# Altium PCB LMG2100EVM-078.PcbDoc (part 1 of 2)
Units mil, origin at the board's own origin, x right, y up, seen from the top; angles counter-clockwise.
Board outline 2400 x 2700 mil, 4 copper layers (Top Layer, MidLayer1, MidLayer2, Bottom Layer), stack 61.2 mil thick; 76 components, 27 nets, 153 pads, 244 vias.
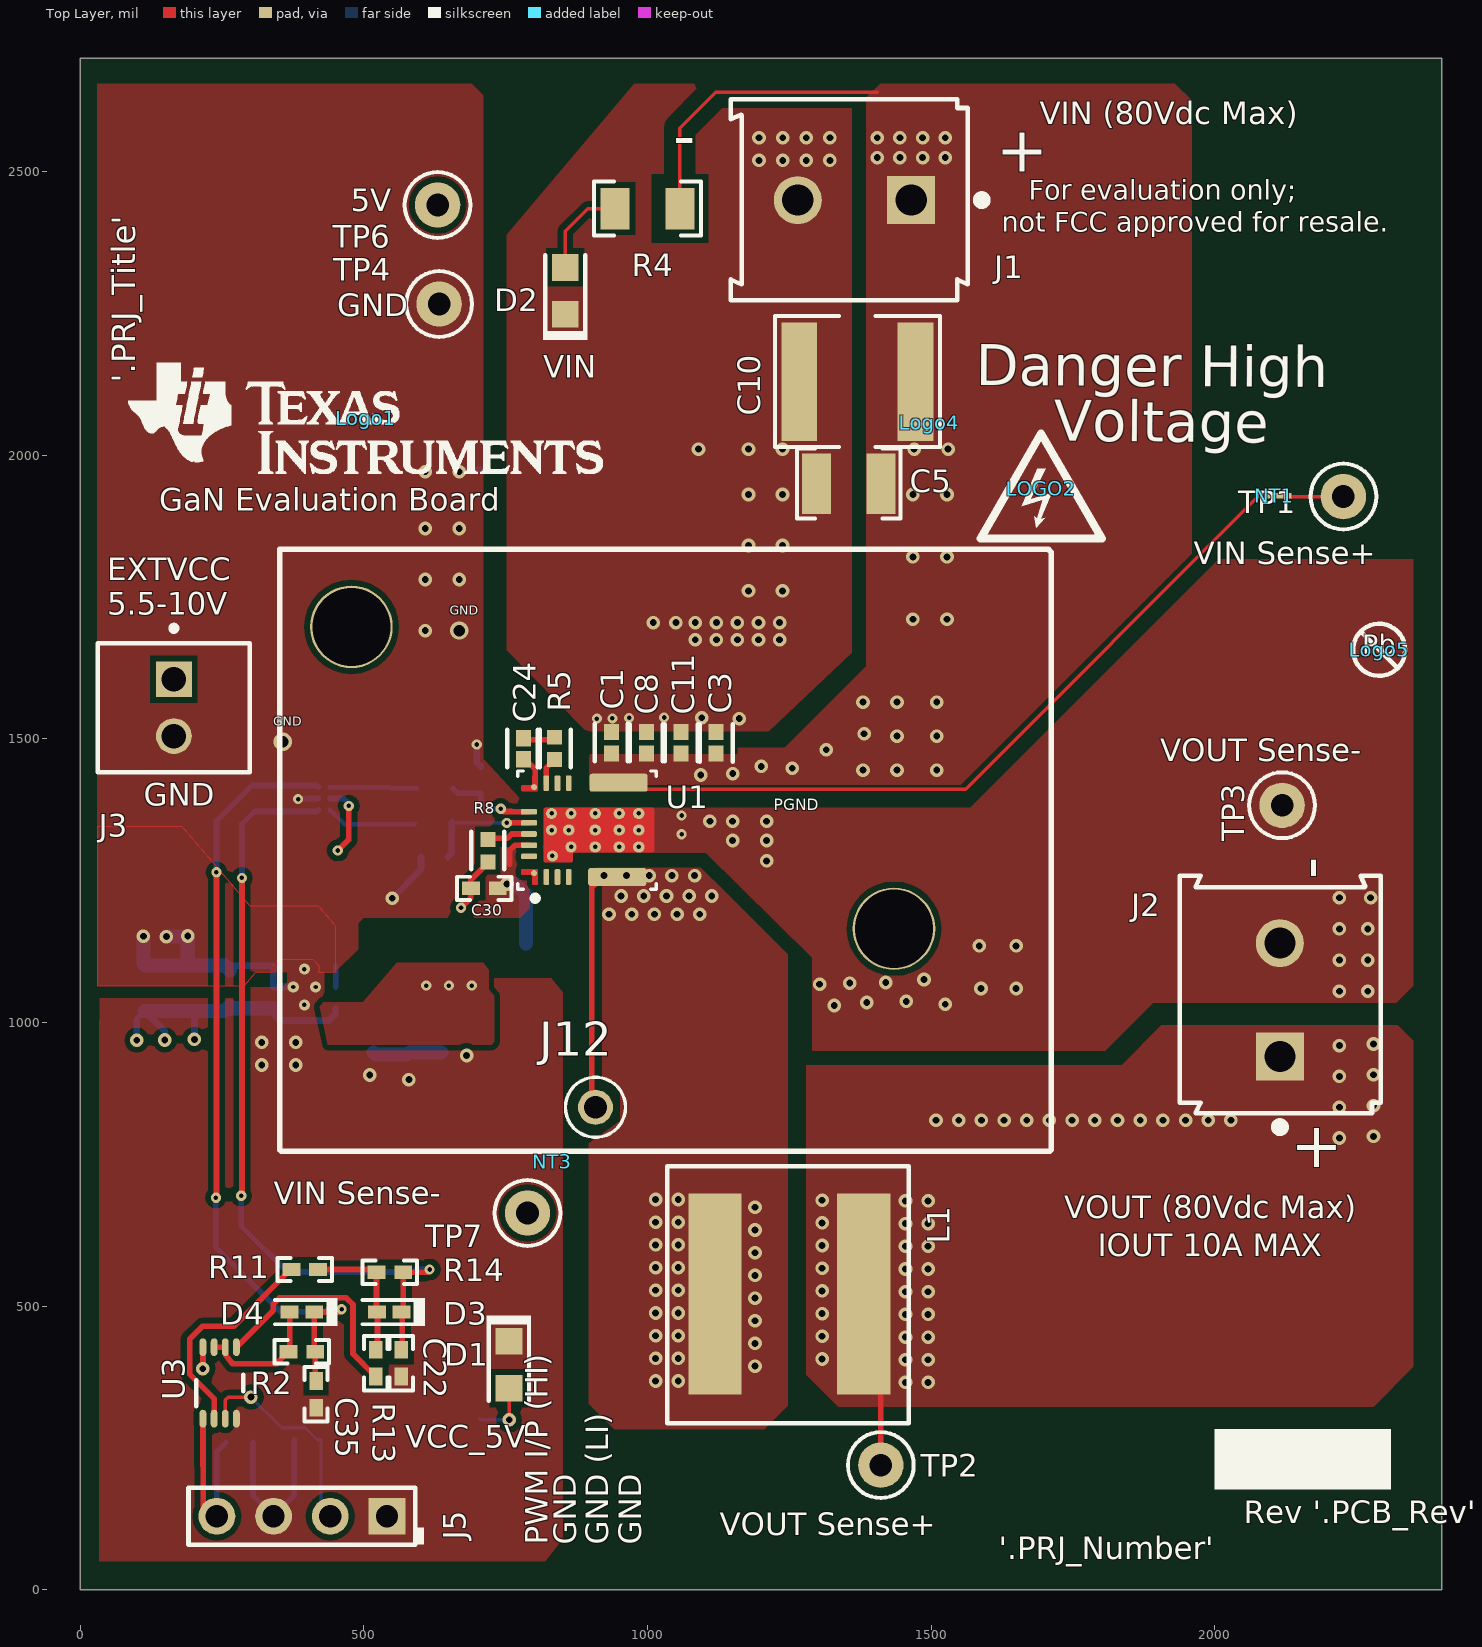
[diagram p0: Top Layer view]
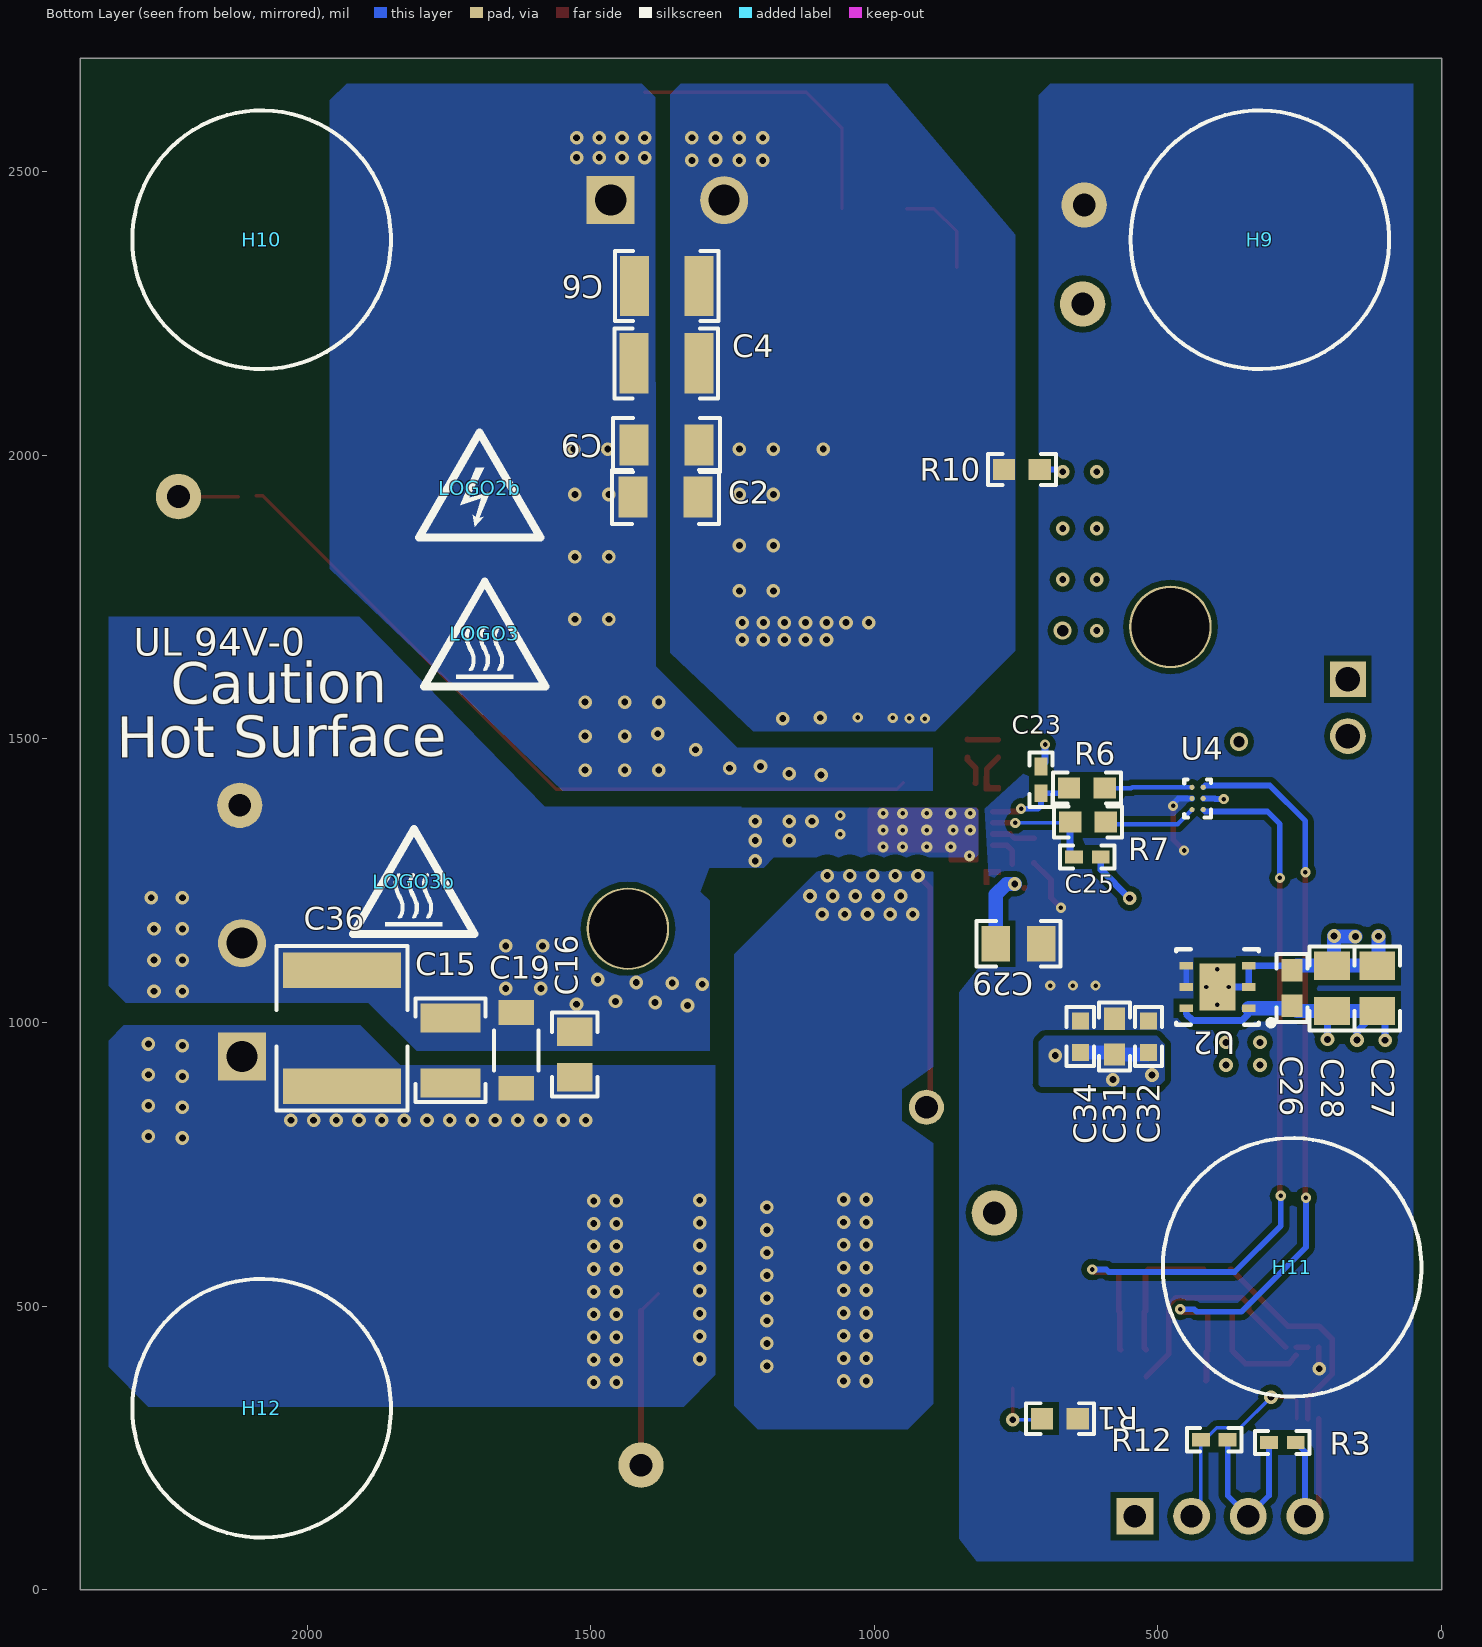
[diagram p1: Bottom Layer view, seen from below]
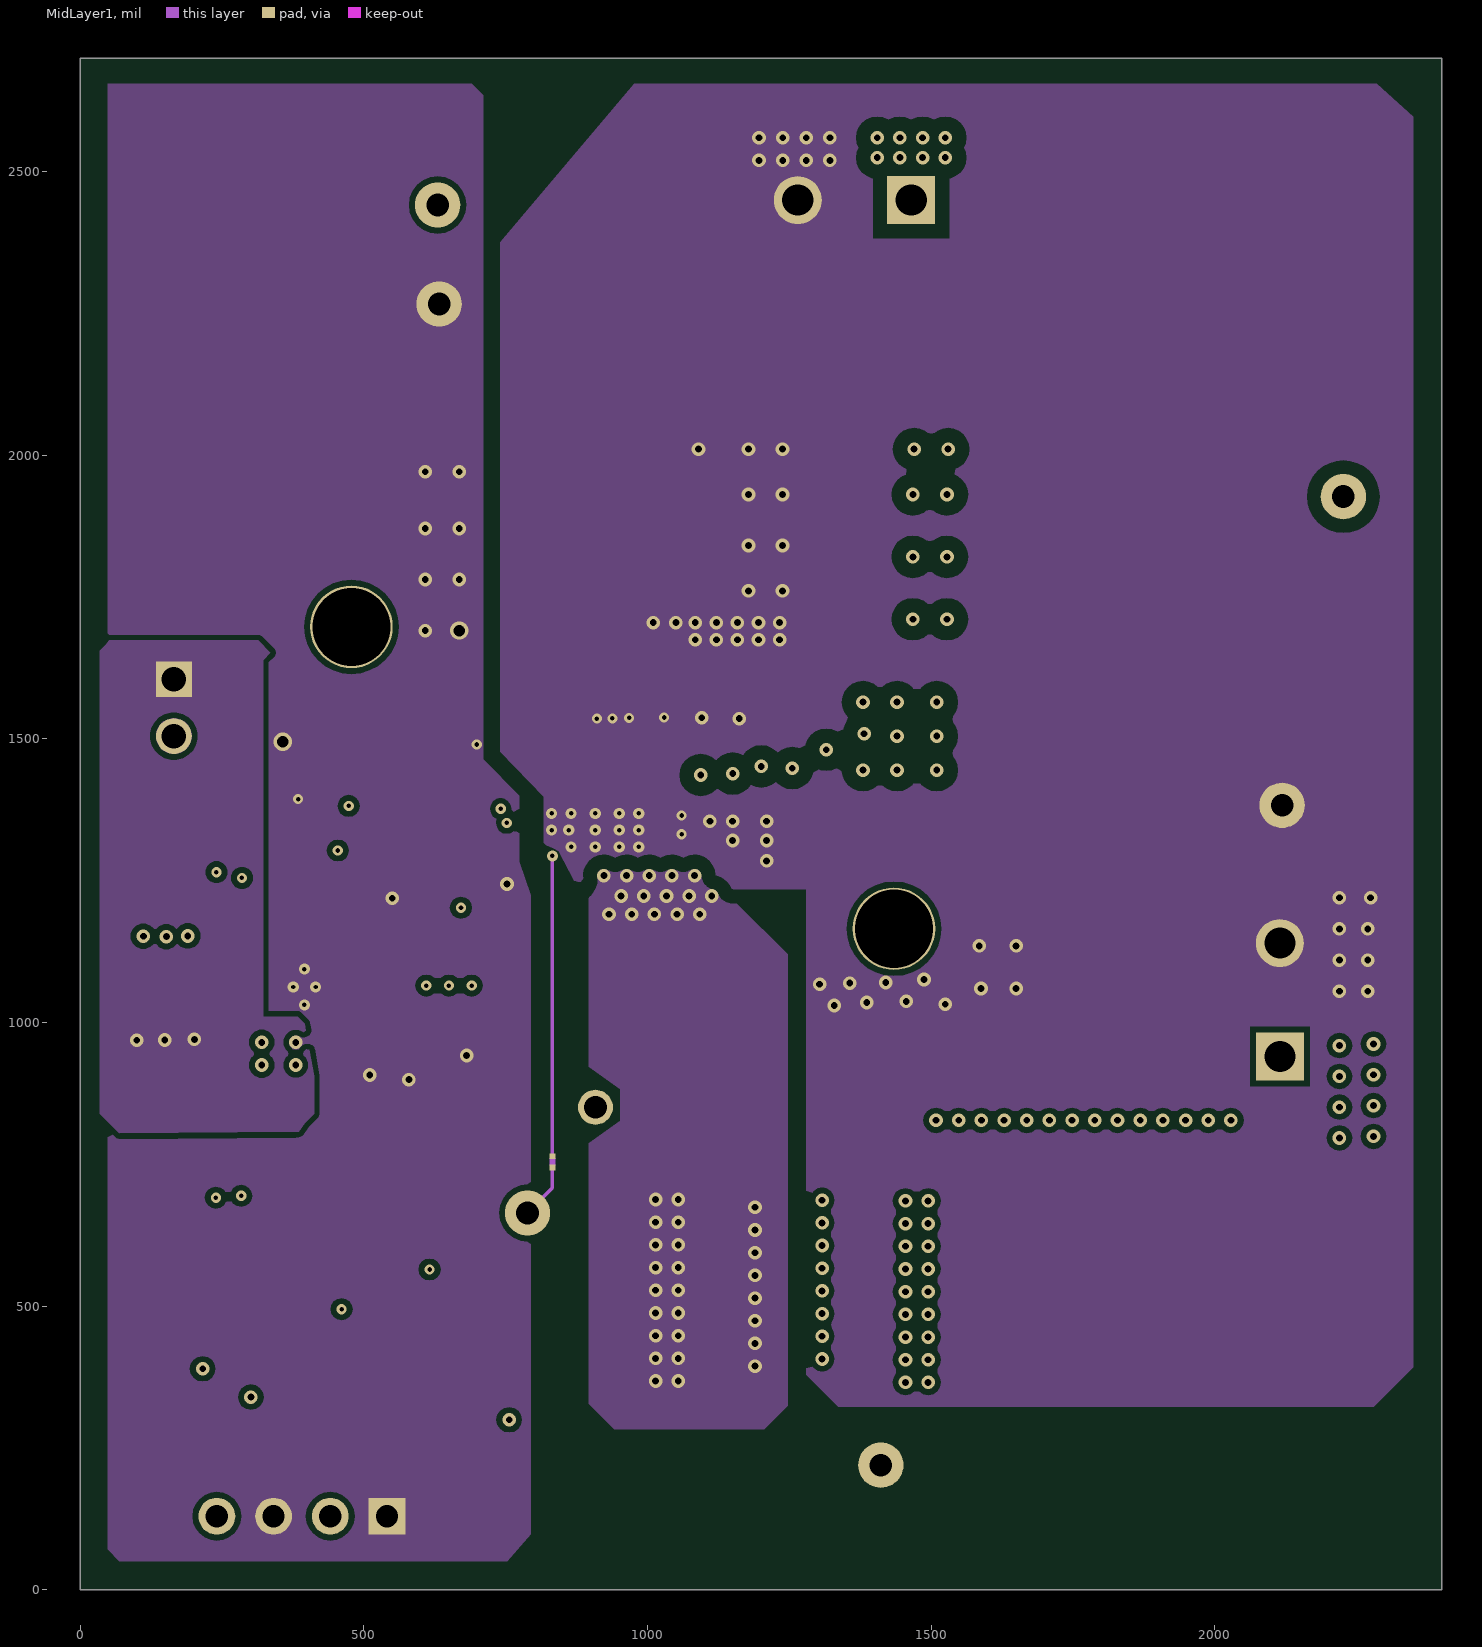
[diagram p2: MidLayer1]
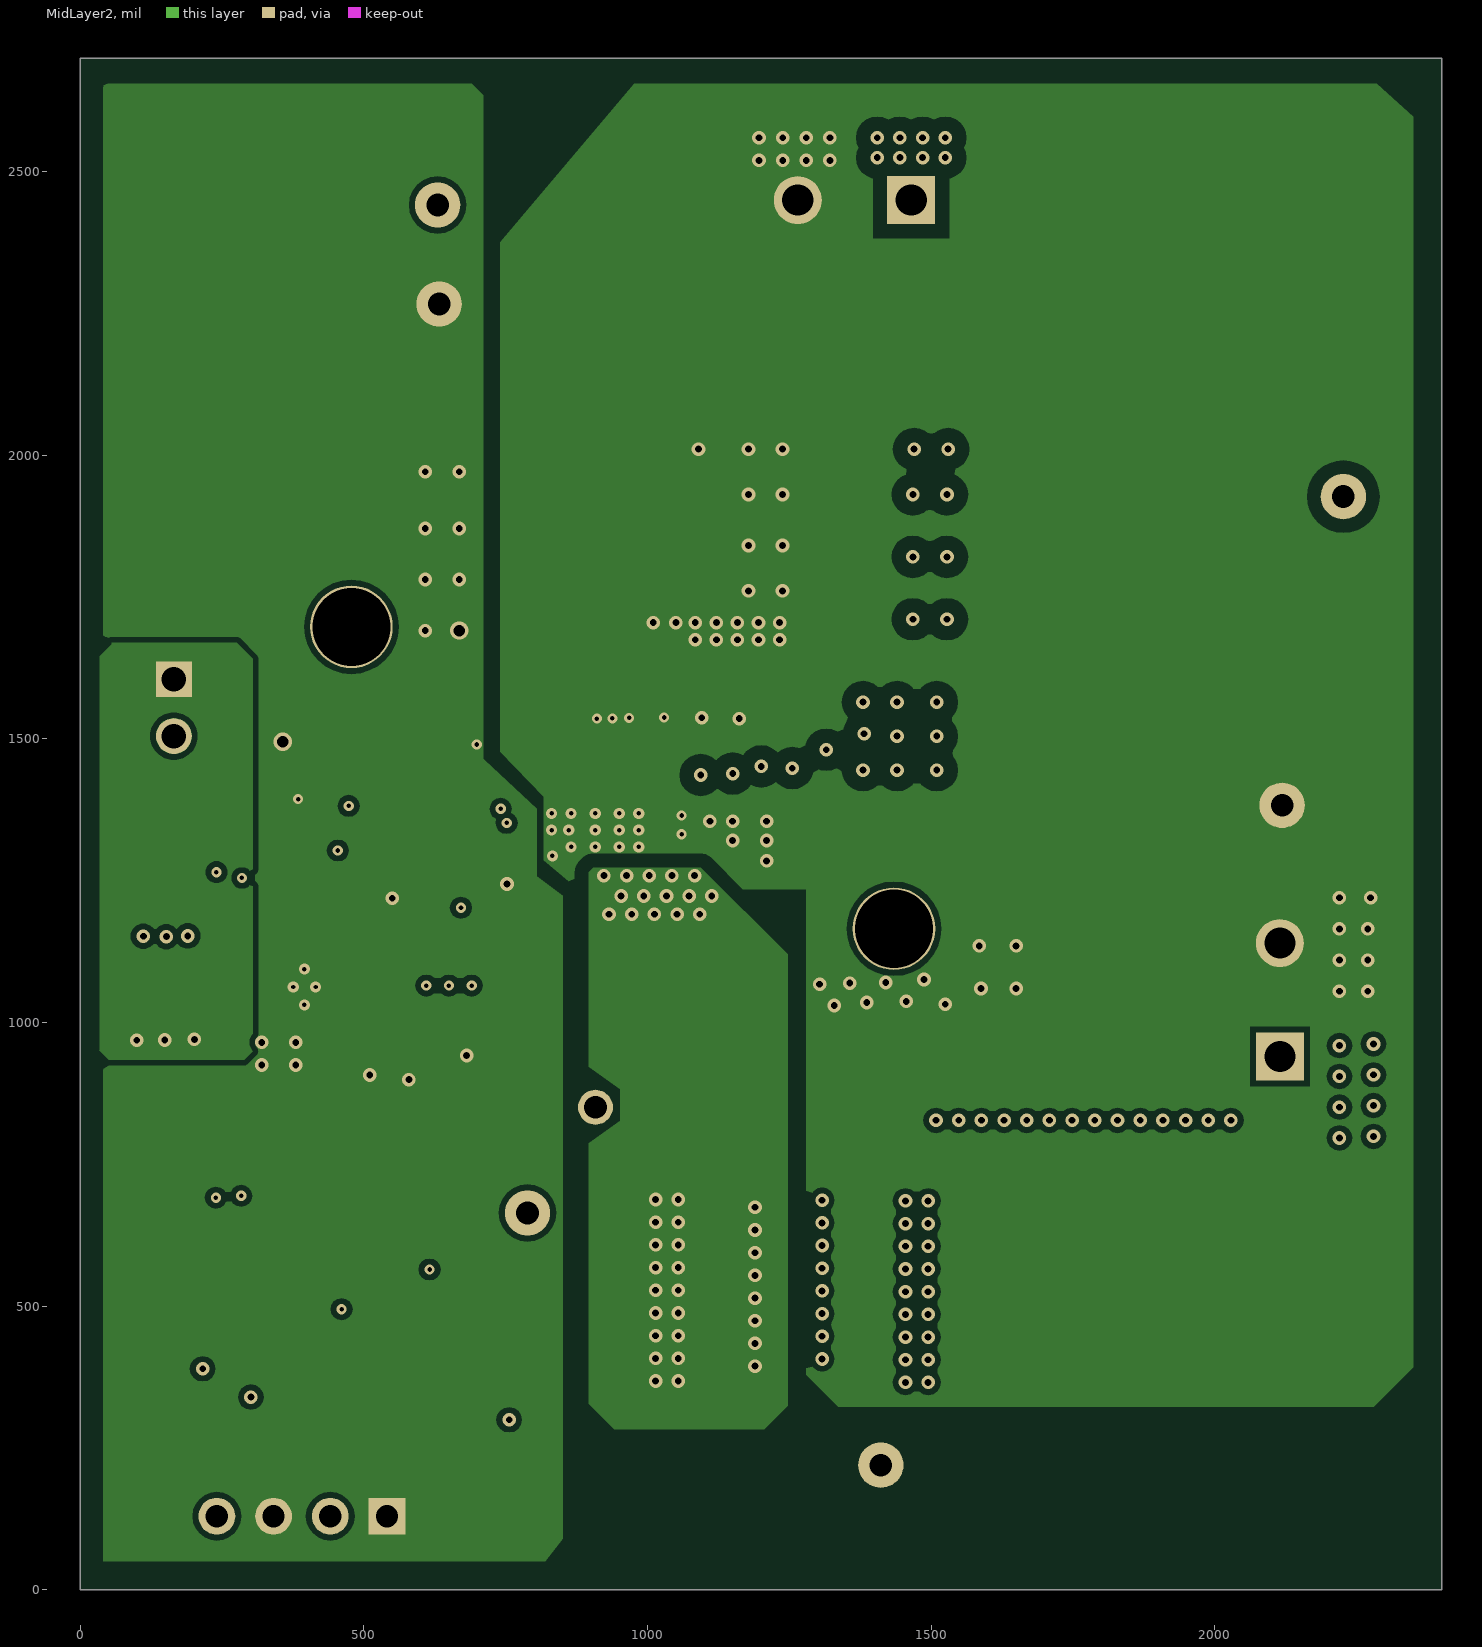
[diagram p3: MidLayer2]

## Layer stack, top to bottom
Top Solder: solder mask 0.4, Solder Resist, Dk 3.5
Top Layer: signal copper 2.8
Dielectric1: core 5, FR-4, Dk 4.8
MidLayer1: signal copper 2.8
Dielectric2: prepreg 40, FR-4, Dk 4.8
MidLayer2: signal copper 2.8
Dielectric3: core 5, FR-4, Dk 4.2
Bottom Layer: signal copper 2.8
Bottom Solder: solder mask 0.4, Solder Resist, Dk 3.5

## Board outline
0,0 2400,0 2400,2700 0,2700

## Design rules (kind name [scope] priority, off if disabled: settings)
AcuteAngle [All] p1 off: minimum=4.50000000000000E+0001 checktracksonly=FALSE
AssemblyTestPointUsage [All] p1 off: valid=2
AssemblyTestpoint [All] p1 off: testpointundercomponent=TRUE minsize=40 maxsize=100 preferedsize=60 minholesize=0 maxholesize=40 preferedholesize=32 testpointgrid=1 usegrid=TRUE gridtolerance=0.01 allowsidetop=TRUE allowsidebottom=TRUE
Clearance Clearance_exception_0_1ufcap [InComponent('C3') vs InComponent('C3')] p1: gap=6 ignorepadtopadclearanceinfootprint=FALSE except(0: Arc-Hole Track-Hole SMDPad-Hole THPad-Hole Via-Hole Fill-Hole Poly-Hole Region-Hole Text-Hole)
Clearance Clearance_exception_0_1ufcap_3 [InComponent('C1') vs InComponent('C1')] p2: gap=6 ignorepadtopadclearanceinfootprint=FALSE except(0: Arc-Hole Track-Hole SMDPad-Hole THPad-Hole Via-Hole Fill-Hole Poly-Hole Region-Hole Text-Hole)
Clearance Clearance_exception_0_1ufcap_2 [InComponent('C8') vs InComponent('C8')] p3: gap=6 ignorepadtopadclearanceinfootprint=FALSE except(0: Arc-Hole Track-Hole SMDPad-Hole THPad-Hole Via-Hole Fill-Hole Poly-Hole Region-Hole Text-Hole)
Clearance Clearance_exception_0_1ufcap_1 [InComponent('C11') vs InComponent('C11')] p4: gap=6 ignorepadtopadclearanceinfootprint=FALSE except(0: Arc-Hole Track-Hole SMDPad-Hole THPad-Hole Via-Hole Fill-Hole Poly-Hole Region-Hole Text-Hole)
Clearance "Schematic Clearance Constraint_2" [InNet('VIN')] p5: gap=25 ignorepadtopadclearanceinfootprint=FALSE except(0: Arc-Hole Track-Hole SMDPad-Hole THPad-Hole Via-Hole Fill-Hole Poly-Hole Region-Hole Text-Hole)
Clearance "Schematic Clearance Constraint_1" [InNet('SW')] p6: gap=25 ignorepadtopadclearanceinfootprint=FALSE except(0: Arc-Hole Track-Hole SMDPad-Hole THPad-Hole Via-Hole Fill-Hole Poly-Hole Region-Hole Text-Hole)
Clearance "Schematic Clearance Constraint" [InNet('K_VIN')] p7: gap=23.6 ignorepadtopadclearanceinfootprint=FALSE except(0: Arc-Hole Track-Hole SMDPad-Hole THPad-Hole Via-Hole Fill-Hole Poly-Hole Region-Hole Text-Hole)
Clearance Clearance_BoardEdge_MountingHoles [OnCopper and InComponentClass('Mounting Holes') vs IsKeepOut] p8: gap=40 ignorepadtopadclearanceinfootprint=FALSE except(0: Arc-Hole Track-Hole SMDPad-Hole THPad-Hole Via-Hole Fill-Hole Poly-Hole Region-Hole Text-Hole)
Clearance Clearance_BoardEdge_Poly [OnCopper and InPoly vs IsKeepOut] p9: gap=25 ignorepadtopadclearanceinfootprint=FALSE except(0: Arc-Hole Track-Hole SMDPad-Hole THPad-Hole Via-Hole Fill-Hole Poly-Hole Region-Hole Text-Hole)
Clearance Clearance_BoardEdge [OnCopper and Not InComponentClass('Logo') and not InComponentClass('FiducialMark') and not InRegion(1000,500,4000,800) and Not IsKeepout vs IsKeepOut] p10: gap=10 ignorepadtopadclearanceinfootprint=FALSE except(0: Arc-Hole Track-Hole SMDPad-Hole THPad-Hole Via-Hole Fill-Hole Poly-Hole Region-Hole Text-Hole)
Clearance Clearance_Poly [InPolygon] p11: gap=10 ignorepadtopadclearanceinfootprint=FALSE except(0: Arc-Hole Track-Hole SMDPad-Hole THPad-Hole Via-Hole Fill-Hole Poly-Hole Region-Hole Text-Hole)
Clearance [All] p12: gap=6 ignorepadtopadclearanceinfootprint=FALSE except(0: Arc-Hole Track-Hole SMDPad-Hole THPad-Hole Via-Hole Fill-Hole Poly-Hole Region-Hole Text-Hole)
ComponentClearance ComponentClearance_Shunt [InComponentClass('Header') vs InComponentClass('Shunt')] p1 off: gap=0 collisioncheckmode=3 verticalgap=0 showdistances=FALSE
ComponentClearance ComponentClearance_Logo [InComponentClass('Logo')] p2: gap=50 collisioncheckmode=3 verticalgap=10 showdistances=FALSE
ComponentClearance ComponentClearance_ScrewToNut [(HasFootprint('NY PMS 440 0025 PH')) vs (HasFootprint('Keystone_1902C'))] p3: gap=0 collisioncheckmode=3 verticalgap=0 showdistances=FALSE
ComponentClearance ComponentClearance_MountingHoles [InComponentClass('Mounting Holes')] p4: gap=0 collisioncheckmode=3 verticalgap=100000 showdistances=FALSE
ComponentClearance ComponentClearance_SmallPassives [HasFootprint('0201*') or HasFootprint('0402*') or HasFootprint('0508') or HasFootprint('0603*') or HasFootprint('0612') or HasFootprint('0805*') or HasFootprint('0815*') or HasFootprint('0830*') or HasFootprint('1206*') or HasFootprint('1210*') or HasFootprint('1808*') or HasFootprint('1812*') or HasFootprint('1825*') or HasFootprint('2010*') or HasFootprint('2220*') or HasFootprint('2225*') or HasFootprint('2512*') or HasFootprint('2728*') or HasFootprint('3518*') vs HasFootprint('0201*') or HasFootprint('0402*') or HasFootprint('0508') or HasFootprint('0603*') or HasFootprint('0612') or HasFootprint('0805*') or HasFootprint('0815*') or HasFootprint('0830*') or HasFootprint('1206*') or HasFootprint('1210*') or HasFootprint('1808*') or HasFootprint('1812*') or HasFootprint('1825*') or HasFootprint('2010*') or HasFootprint('2220*') or HasFootprint('2225*') or HasFootprint('2512*') or HasFootprint('2728*') or HasFootprint('3518*')] p5: gap=20 collisioncheckmode=3 verticalgap=10 showdistances=FALSE
ComponentClearance ComponentClearance_THtoSMT [IsThruComponent vs IsSMTComponent] p6: gap=40 collisioncheckmode=3 verticalgap=0 showdistances=FALSE
ComponentClearance ComponentClearance_THtoTH [IsThruComponent vs IsThruComponent] p7: gap=50 collisioncheckmode=3 verticalgap=0 showdistances=FALSE
ComponentClearance [All] p8: gap=30 collisioncheckmode=3 verticalgap=10 showdistances=FALSE
DiffPairsRouting [All] p1 off: maxlimit=100 minlimit=10 mostfreqgap=10 toplayer_minwidth=15 toplayer_maxwidth=15 toplayer_prefwidth=15 midlayer1_minwidth=15 midlayer1_maxwidth=15 midlayer1_prefwidth=15 midlayer2_minwidth=15 midlayer2_maxwidth=15 midlayer2_prefwidth=15 bottomlayer_minwidth=15 bottomlayer_maxwidth=15 bottomlayer_prefwidth=15 maxuncoupledlength=1000
FabricationTestPointUsage TestPointUsage [All] p1: valid=2 allowmultiple=FALSE
FabricationTestpoint Testpoint [All] p1: side=3 testpointundercomponent=TRUE minsize=40 maxsize=100 preferedsize=60 minholesize=0 maxholesize=40 preferedholesize=32 testpointgrid=1 allowsidetop=TRUE allowsidebottom=TRUE usegrid=TRUE gridtolerance=0.01
FanoutControl Fanout_LCC [IsLCC] p1 off: bgadir=Out bgaviamode=Centered fanoutstyle=Auto fanoutdirection=Alternating viagrid=1 // Fanout_LCC (Default Rule)
FanoutControl Fanout_BGA [IsBGA] p2: bgadir=Out bgaviamode=Centered fanoutstyle=Auto fanoutdirection=Alternating viagrid=1 // Fanout_BGA (Default Rule)
FanoutControl Fanout_Default [All] p4: bgadir=Out bgaviamode=Centered fanoutstyle=Auto fanoutdirection=Alternating viagrid=1 // Fanout_Default (Default Rule)
FanoutControl Fanout_Small [(CompPinCount < 5)] p5: bgadir=Out bgaviamode=Centered fanoutstyle=Auto fanoutdirection=OutThenIn viagrid=1 // Fanout_Small (Default Rule)
Height [All] p1 off: minheight=0 maxheight=1000 prefheight=500
HoleSize [All] p1: absolutevalues=TRUE maxlimit=251 minlimit=7 maxpercent=80.000 minpercent=20.000
HoleToHoleClearance [All] p1: gap=6 allowstackedmicrovias=TRUE
MinimumAnnularRing MinimumAnnularRing_ThermalPadVias [IsVia and InAnyComponent] p1: minimumring=5
MinimumAnnularRing [All] p2: minimumring=5
MinimumSolderMaskSliver MinimumSolderMaskSliver_Logo [InComponentClass('Logo') vs InComponentClass('Logo')] p1: minsoldermaskwidth=0.7
MinimumSolderMaskSliver MinimumSolderMaskSliver_DCU [HasFootprint('DCU0008A_N') vs HasFootprint('DCU0008A_N')] p2: minsoldermaskwidth=3.9
MinimumSolderMaskSliver [All] p3: minsoldermaskwidth=4
NetAntennae [All And Not InNet(SW)] p1: netantennaetolerance=0
PlaneConnect [All] p1: planeconnectstyle=Direct reliefexpansion=10 reliefentries=4 reliefconductorwidth=10 reliefairgap=10
PolygonConnect [All] p1: connectstyle=Direct reliefconductorwidth=10 reliefentries=4 polygonreliefangle="90 Angle" airgapwidth=10
RoutingCorners "Schematic Routing Corners_2" [InNet('VIN')] p1: cornerstyle=45-Degree minsetback=100 maxsetback=100
RoutingCorners "Schematic Routing Corners_1" [InNet('SW')] p2: cornerstyle=45-Degree minsetback=100 maxsetback=100
RoutingCorners "Schematic Routing Corners" [InNet('K_VIN')] p3: cornerstyle=45-Degree minsetback=100 maxsetback=100
RoutingCorners [All] p4: cornerstyle=45-Degree minsetback=100 maxsetback=100
RoutingVias ThermalPadVias [IsVia and InAnyComponent] p1: holewidth=7.87 width=19.68 viastyle="Through Hole" minholewidth=7 minwidth=19.68 maxholewidth=12.99 maxwidth=23.62
RoutingVias [All] p2: holewidth=16 width=18 viastyle="Through Hole" minholewidth=7 minwidth=18 maxholewidth=40 maxwidth=65
SMDToCorner [All] p1: distance=30000
SilkToSilkClearance [All] p1 off: silktosilkclearance=5
SilkToSolderMaskClearance SilkscreenOverComponentPads [IsPad] p1 off: minsilkscreentomaskgap=5 clearancetoexposedcopper=TRUE
SolderMaskExpansion [All] p1: expansion=1.97 istentingtop=FALSE
Width [All] p1: maxlimit=100 minlimit=5 preferedwidth=6 midlayer1_minwidth=6 midlayer2_minwidth=6 bottomlayer_minwidth=6 minimp=50.000000 maximp=50.000000 favimp=50.000000 checkconnectedcopper=TRUE
11 further rules are at their usual default settings.

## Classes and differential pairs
component class Header: J5
component class LMG2100EVM: C1 C2 C3 C4 C5 C6 C8 C9 C10 C11 C15 C16 C19 C22 C23 C24 C25 C26 C27 C28 C29 C30 C31 C32 C34 C35 C36 D1 D2 D3 D4 J1 J2 J3 J5 J12 L1 NT1 R1 R2 R3 R4 R5 R6 R7 R8 R10 R11 R12 R13 R14 TP1 TP2 TP3 TP4 TP6 TP7 U1 U2 U3 U4
component class AssemblyNote: ZZ2 ZZ3 ZZ4
component class LMG2100EVM_HW: H9 H10 H11 H12 Logo1 LOGO2 LOGO2b LOGO3 LOGO3b Logo4 Logo5 ZZ2 ZZ3 ZZ4
component class Logo: Logo1

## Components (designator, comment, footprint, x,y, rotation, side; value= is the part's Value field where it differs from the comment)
C1 "0.1uF" FP-GRM155-0_05-IPC_A 936.37,1493.53 r90 top
C2 "C3216X7R2A105M160AA" 1206 1368.18,1926.68 r0 bottom value=1uF
C3 "0.1uF" FP-GRM155-0_05-IPC_A 1120.96,1492.95 r90 top
C4 "GRM32ER72A225KA35L" 1210_270 1366.63,2162.26 r180 bottom value=2.2uF
C5 "GRM32ER72A225KA35L" 1210_270 1355,1950 r180 top value=2.2uF
C6 "GRM32ER72A225KA35L" 1210_270 1365.86,2298.65 r180 bottom value=2.2uF
C8 "0.1uF" FP-GRM155-0_05-IPC_A 997.84,1493.16 r90 top
C9 "C3216X7R2A105M160AA" 1206 1366.63,2018.12 r0 bottom value=1uF
C10 "22201C106MAT2A" 2220_280 1370,2130 r0 top value=10uF
C11 "0.1uF" FP-GRM155-0_05-IPC_A 1059.5,1493.33 r90 top
C15 "C3225X7S2A475K200AE" 1210 1747.2,950.77 r90 bottom value=4.7uF
C16 "C2012X7S2A105K125AB" 0805_HV 1528.07,943.64 r90 bottom value=1uF
C19 "C3216X7S2A335M160AB" 1206_190 1631.41,950.78 r90 bottom value=3.3uF
C22 "CC0402JRNPO9BN101" 0402 565.72,399.52 r270 top value=100pF
C23 "GRM1555C1H100JA01D" 0402 706.2,1427.78 r270 bottom value=10pF
C24 "0.1uF 10V" FP-C1005-050-0_05-IPC_A 781.5,1482.9 r270 top
C25 "GRM1555C1H100JA01D" 0402 624.42,1291.8 r180 bottom value=10pF
C26 "0603YC104JAT2A" 0603 263.4,1060.8 r90 bottom value=0.1uF
C27 "C2012X5R1E106K125AB" 0805_HV 113.2,1060.3 r270 bottom value=10uF
C28 "C0805C225K4RACTU" 0805_HV 193.2,1060.3 r270 bottom value=2.2uF
C29 "C0805C225K4RACTU" 0805_HV 745.84,1139.06 r180 bottom value=2.2uF
C30 "C1005X5R1E105K050BC" 0402 712.29,1236.5 r0 top value=1uF
C31 "06033C101KAT2A" 0603 576.78,975 r90 bottom value=100pF
C32 "GRM188R71A225KE15D" 0603_HV 516.85,975 r270 bottom value=2.2uF
C34 "GRM188R71A225KE15D" 0603_HV 636.85,975 r270 bottom value=2.2uF
C35 "CC0402JRNPO9BN101" 0402 415.72,344.52 r270 top value=100pF
C36 "C5750X7S2A156M250KB" 2220_280 1938.72,989.89 r90 bottom value=15uF
D1 "VCC_5V" LTST-C170KGKT_Green 755.66,396.52 r90 top value=Green
D2 "VIN" LTST-C170KGKT_Green 855,2290 r270 top value=Green
D3 "SDM03U40-7" SOD-523 544.72,489.52 r180 top value=40V
D4 "SDM03U40-7" SOD-523 390.72,489.52 r180 top value=40V
H9 "SJ-5303 (CLEAR)" Bumpon_SJ5003Transparent 320.36,2380 r180 bottom
H10 "SJ-5303 (CLEAR)" Bumpon_SJ5003Transparent 2080.36,2380 r180 bottom
H11 "SJ-5303 (CLEAR)" Bumpon_SJ5003Transparent 263.45,568.21 r180 bottom
H12 "SJ-5303 (CLEAR)" Bumpon_SJ5003Transparent 2080.36,320 r180 bottom
J1 "VIN (80Vdc Max)" TEC_282841-2 1365,2450 r180 top
J2 "VOUT (80Vdc Max)" TEC_282841-2 2115,1040 r90 top
J3 "282834-2" TEC_282834-2 165,1555 r270 top
J5 "5-146278-4" TE_5-146278-4 390.72,129.52 r180 top
J12 "5004" FP-5004-MFG 908.28,850.57 r0 top locked
L1 "XAL1010-472ME" XAL8080 1250.2,521.62 r0 top value=4.7uH
Logo1 "Texas Instruments" TI_Stacked_Overlay_Small 503.13,2065.35 r0 top
LOGO2 "DANGER HIGH VOLTAGE" IEC_HighVoltage_Small 1694,1941 r0 top
LOGO2b "DANGER HIGH VOLTAGE" IEC_HighVoltage_Small 1696,1943 r180 bottom
LOGO3 "CAUTION HOT SURFACE" IEC_HotSurface_Small 1686.93,1685.33 r180 bottom
LOGO3b "CAUTION HOT SURFACE" IEC_HotSurface_Small 1812,1249 r180 bottom
Logo4 "FCC disclaimer" FCC_disclaimer_stacked 1496.63,2057.8 r0 top
Logo5 "Pb-Free Symbol" Pb-Free_Overlay_Small 2290,1657 r0 top
NT1 "Net-Tie" Net-Tie_10milWide_30milLong 2105.18,1928.68 r0 top net-tie
NT3 "Net-Tie" Net-Tie_10mil 832.43,754.41 r90 top net-tie (schematic designator NT2)
R1 "CRCW06031K00JNEA" 0603 673.02,301.49 r0 bottom value=1.0k
R2 "CRCW040247R0JNED" 0402 390.72,419.52 r0 top value=47
R3 "CRCW040210K0FKED" 0402 280.72,259.52 r0 bottom value=10.0k
R4 "CRCW120620K0JNEA" 1206 1000,2435 r180 top value=20k
R5 "6.04Ω, 0402" FP-CRCW0402-e3-IPC_A 835.7,1483.2 r270 top
R6 "CRCW06030000Z0EA" 0603 625.2,1413.3 r180 bottom value=0
R7 "CRCW06030000Z0EA" 0603 623.3,1353.4 r180 bottom value=0
R8 "6.04Ω, 0402" FP-CRCW0402-e3-IPC_A 718.44,1303.04 r90 top
R10 "CRCW06030000Z0EA" 0603 740,1975 r180 bottom value=0
R11 "CRCW04020000Z0ED" 0402 395.72,564.52 r180 top value=0
R12 "CRCW04020000Z0ED" 0402 400.72,264.52 r0 bottom value=0
R13 "CRCW04020000Z0ED" 0402 520.72,399.52 r90 top value=0
R14 "CRCW040247R0JNED" 0402 545.72,559.52 r0 top value=47
TP1 "5000" Keystone5000 2226.98,1927.26 r0 top value=Red
TP2 "VOUT Sense+" Keystone5000 1411.4,219.57 r0 top value=Red
TP3 "VOUT Sense-" Keystone5001 2118.9,1383 r0 top value=Black
TP4 "5001" Keystone5001 632.69,2266.74 r0 top value=Black
TP6 "5004" Keystone5004 629.98,2441.4 r0 top
TP7 "5001" Keystone5001 788.43,664.18 r0 top value=Black
U1 "LMG2100R044" RAR0016A-MFG 893.5,1339.21 r90 top
U2 "LP38690SD-5.0/NOPB" SDE06A_full 395.12,1062.6 r0 bottom
U3 "SN74LVC3G14DCUR" DCU0008A_N 245.72,364.52 r90 top
U4 "SN74LVC2G14YZPR" YZP0006ADBD 430,1395 r0 bottom
ZZ2 "These assemblies are ESD sensitive, ESD precautions shall be observed." AssemblyNote -715,3834.11 r0 top
ZZ3 "These assemblies must be clean and free from flux and all contaminants. Use of no clean flux is not acceptable." AssemblyNote -715,3745.56 r0 top
ZZ4 "These assemblies must comply with workmanship standards IPC-A-610 Class 2, unless otherwise specified." AssemblyNote -715,3657 r0 top

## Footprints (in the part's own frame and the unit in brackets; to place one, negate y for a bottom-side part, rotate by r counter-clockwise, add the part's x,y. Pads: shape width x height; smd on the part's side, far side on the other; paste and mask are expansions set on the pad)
0402 [mm] "0402 from SM-752 data"
  rect 0.8x0.6 smd: 1(-0.6,0) 2(0.6,0)
  silkscreen extent -1.22,-0.52 1.22,0.52, body extent -0.55,-0.3 0.55,0.3, height 0.6
0603 [mm] "0603 from SM-752 data"
  rect 1x0.95 smd: 1(-0.8,0) 2(0.8,0)
  silkscreen extent -1.52,-0.69 1.52,0.69, body extent -0.87,-0.47 0.87,0.47, height 1
0603_HV [mil] "Ernesto recommended land pattern.  26 mil between pads."
  rect 30x30 smd: 1(-28,0) 2(28,0)
  silkscreen extent -52,-24 52,24, body extent -34,-19 34,19, height 39
0805_HV [mil] "0805 with 30mil clearance between pads"
  rect 50x63 smd: 1(-40,0) 2(40,0)
  silkscreen extent -74,-40 74,40, body extent -43,-29 43,29, height 57
1206 [mm] "1206 from SM-752 data"
  rect 1.3x1.85 smd: 1(-1.45,0) 2(1.45,0)
  silkscreen extent -2.4,-1.21 2.4,1.21, body extent -1.7,-0.9 1.7,0.9, height 1.35
1206_190 [mm] "1206_190"
  rect 1.1x1.6 smd: 1(-1.7,0) 2(1.7,0)
  silkscreen extent -0.9,-1 0.9,1, body extent -1.75,-0.95 1.75,0.95, height 1.9
1210 [mm] "1210 from SM-752 data"
  rect 1.3x2.7 smd: 1(-1.45,0) 2(1.45,0)
  silkscreen extent -2.32,-1.57 2.32,1.57, body extent -1.7,-1.35 1.7,1.35, height 1.35
1210_270 [mm] "1210"
  rect 1.3x2.7 smd: 1(-1.45,0) 2(1.45,0)
  silkscreen extent -2.32,-1.57 2.32,1.57, body extent -1.7,-1.35 1.7,1.35, height 2.7
2220_280 [mm] "Chip Capacitor, Body 5.7x5.0mm, IPC Medium Density"
  rect 1.6x5.3 smd: 1(-2.6,0) 2(2.6,0)
  silkscreen extent -3.69,-2.94 3.69,2.94, body extent -2.95,-2.62 2.95,2.62, height 2.8
AssemblyNote [mil] "Assembly Note"
Bumpon_SJ5003Transparent [mil] "3M Hemispherical Bumpon transparent"
  round 1 on Mech4: 0(0,0)
  silkscreen extent -228,-228 228,228, body extent -219,-219 219,219, height 197
DCU0008A_N [mm] "TSSOP, 8-Leads, Body 2x2.3mm, Pitch 0.5mm, IPC Medium Density"
  oval 0.8x0.3 smd: 1(-1.6,0.75) 2(-1.6,0.25) 3(-1.6,-0.25) 4(-1.6,-0.75) 5(1.6,-0.75) 6(1.6,-0.25) 7(1.6,0.25) 8(1.6,0.75)
  silkscreen extent -1.05,-1.05 0.38,1.05, body extent -1.56,-1 1.56,1, height 0.9
FCC_disclaimer_stacked [mil]
FP-5004-MFG [mm]
  round 1.57 hole 1.02 paste-2539.97 mask+0: 1(0,0)
  silkscreen extent -1.35,-1.34 1.35,1.34, body extent -1.27,-1.26 1.27,1.26, height 4.71
FP-C1005-050-0_05-IPC_A [mil]
  rect 29.11x26.48 smd paste+0 mask+0: 1(-18.37,0) 2(18.37,0)
  silkscreen extent -33,-29 33,29, body extent -41,-21 41,21, height 10
FP-CRCW0402-e3-IPC_A [mil]
  rect 26.31x26.48 smd paste+0 mask+0: 1(-19.77,0) 2(19.77,0)
  silkscreen extent -33,-29 33,29, body extent -41,-21 41,21, height 10
FP-GRM155-0_05-IPC_A [mil]
  rect 28.16x26.48 smd paste+0 mask+0: 1(-18.84,0) 2(18.84,0)
  silkscreen extent -33,-29 33,29, body extent -41,-21 41,21, height 10
IEC_HighVoltage_Small [mil]
  silkscreen extent -107,-88 107,97
IEC_HotSurface_Small [mil]
  silkscreen extent -107,-93 107,92
Keystone5000 [mil] "For Keystone 500x miniature loop terminals"
  round 80 hole 40: 1(0,0)
  silkscreen extent -58,-58 58,58, body extent -49,-49 49,49, height 182
Keystone5001 [mil] "For Keystone 500x miniature loop terminals"
  round 80 hole 40: 1(0,0)
  silkscreen extent -58,-58 58,58, body extent -49,-49 49,49, height 182
Keystone5004 [mil] "For Keystone 500x miniature loop terminals"
  round 80 hole 40: 1(0,0)
  silkscreen extent -58,-58 58,58, body extent -49,-49 49,49, height 182
LTST-C170KGKT_Green [mm] "LITE-ON"
  rect 1.2x1.2 smd: 1(-1.05,0) 2(1.05,0)
  silkscreen extent -1.6,-1 2.2,1, body extent -1.05,-0.67 1.05,0.67, height 1.1
Net-Tie_10mil [mil] "10mil net tie, no solder mask opening, no solder paste"
  rect 10x10 on Mid1 paste-5 mask-5: 1(-10,0) 2(10,0)
  MidLayer1 region: -6,-5 6,-5 6,5 -6,5
Net-Tie_10milWide_30milLong [mil] "10mil net tie, no solder mask opening, no solder paste"
  rect 30x10 smd paste-5 mask-5: 1(-15,0) 2(15,0)
Pb-Free_Overlay_Small [mil]
  silkscreen extent -46,-46 46,46
RAR0016A-MFG [mm]
  round 0.265 smd paste+0 mask-1000: 1(-1.925,2.375) 11(1.925,2.375)
  rrect40% 0.7x0.25 smd paste+0 mask-1000: 2(-2.1,1.825) 3(-2.1,1.325) 4(-2.1,0.825) 8(2.1,0.825) 9(2.1,1.325) 10(2.1,1.825)
  rrect25% 0.8x2.6 smd paste-1000 mask-1000: 5(-2.1,-1.35) 7(2.125,-1.412)
  rrect40% 0.25x0.7 smd paste+0 mask-1000: 12(0.825,2.6) 13(0.325,2.6) 14(-0.175,2.6) 15(-0.675,2.6) 16(-1.175,2.6)
  Top Layer region: -1.45,1.85 -1.437,1.9 -1.4,1.937 -1.35,1.95 -1.35,1.95 0.9,1.95 0.938,1.942 0.971,1.921 0.992,1.888 1,1.85 1,1.85 1,-2.9 0.987,-2.95 0.95,-2.987 0.9,-3 0.9,-3 -0.9,-3 -0.95,-2.987 -0.987,-2.95 -1,-2.9 -1,-2.9 -1,0.585 -1.004,0.604 -1.015,0.62 -1.031,0.631 -1.05,0.635 -1.05,0.635 -1.35,0.635 -1.388,0.643 -1.421,0.664 -1.442,0.697 -1.45,0.735 -1.45,0.735
  Top Layer region: 2.4,2.2 2.419,2.204 2.435,2.215 2.446,2.231 2.45,2.25 2.45,2.25 2.45,2.4 2.443,2.425 2.425,2.443 2.4,2.45 2.4,2.45 2.1,2.45 2.062,2.458 2.029,2.479 2.008,2.512 2,2.55 2,2.55 2,2.9 1.993,2.925 1.975,2.943 1.95,2.95 1.95,2.95 1.8,2.95 1.775,2.943 1.757,2.925 1.75,2.9 1.75,2.9 1.75,2.25 1.754,2.231 1.765,2.215 1.781,2.204 1.8,2.2 1.8,2.2
  Top Layer region: -2.4,2.2 -2.419,2.204 -2.435,2.215 -2.446,2.231 -2.45,2.25 -2.45,2.25 -2.45,2.4 -2.443,2.425 -2.425,2.443 -2.4,2.45 -2.4,2.45 -2.1,2.45 -2.062,2.458 -2.029,2.479 -2.008,2.512 -2,2.55 -2,2.55 -2,2.9 -1.993,2.925 -1.975,2.943 -1.95,2.95 -1.95,2.95 -1.8,2.95 -1.781,2.946 -1.765,2.935 -1.754,2.919 -1.75,2.9 -1.75,2.9 -1.75,2.25 -1.754,2.231 -1.765,2.215 -1.781,2.204 -1.8,2.2 -1.8,2.2
  silkscreen extent -3.17,-3.1 2.65,3.1, body extent -2.6,-3.1 2.6,3.05, height 0.25
SDE06A_full [mm] "SON, 6-Leads, Body 3x3 mm, Pitch 0.95mm, Full Paste, NSC Recommended"
  rect 0.6x0.35 smd paste-0.175 mask+0.051: 1(-1.4,0.95) 2(-1.4,0) 3(-1.4,-0.95) 4(1.4,-0.95) 5(1.4,0) 6(1.4,0.95)
  rect 1.6x2.1 smd paste-0.8 mask+0.051: 7(0,0)
  silkscreen extent -2.52,-1.7 1.85,1.72, body extent -1.55,-1.55 1.55,1.55, height 0.8
SOD-523 [mm] "NXP Semiconductor recommended land pattern, nominal STEP model"
  rect 0.8x0.6 smd paste-0.05: 1(-0.55,0) 2(0.55,0)
  silkscreen extent -1.6,-0.64 1.2,0.63, body extent -0.8,-0.4 0.8,0.4, height 0.72
TE_5-146278-4 [mm] "TE CONNECTIVITY"
  rect 1.65x1.65 hole 1: 1(-3.81,0)
  round 1.65 hole 1: 2(-1.27,0) 3(1.27,0) 4(3.81,0)
  silkscreen extent -5.46,-1.27 5.08,1.27, body extent -4.95,-1.17 4.95,1.17, height 8.13
TEC_282834-2 [mm] "TEC"
  rect 1.6x1.6 hole 1.1: 1(-1.27,0)
  round 1.6 hole 1.1: 2(1.27,0)
  silkscreen extent -3.66,-3.4 2.9,3.4, body extent -2.77,-3.25 2.77,3.25, height 10.01
TEC_282841-2 [mm] "TE Connectivity"
  rect 2.15x2.15 hole 1.4: 1(-2.54,0)
  round 2.15 hole 1.4: 2(2.54,0)
  silkscreen extent -5.9,-4.52 5.55,4.47, body extent -5.08,-4.52 5.58,4.48, height 15.2
TI_Stacked_Overlay_Small [mil]
  silkscreen extent -418,-98 418,98
XAL8080 [mm] "Coilcraft"
  rect 2.38x9 smd: 1(-3.33,0) 2(3.33,0)
  silkscreen extent -5.48,-5.8 5.34,5.72, body extent -4.15,-4.4 4.15,4.4, height 8
YZP0006ADBD [mm] "BGA, 6-Leads, Pitch 0.5mm"
  round 0.23 smd paste-0.12: A1(-0.25,0.5) A2(0.25,0.5) B1(-0.25,0) B2(0.25,0) C1(-0.25,-0.5) C2(0.25,-0.5)
  silkscreen extent -0.6,-0.85 0.6,0.85, body extent -0.46,-0.71 0.46,0.71, height 0.51

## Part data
C1 C3 C8 C11: library part CMP-06035-008289-1, "Chip Multilayer Ceramic Capacitors for General Purpose, 0402, 0.10uF, X5R, 15%, 10%, 100V", Capacitance=100nF, Case Code (Imperial)=0402, Case Code (Metric)=1005, Dielectric=X5R, Max Operating Temperature=85°C, Min Operating Temperature=-55°C, Package Quantity=10000, Tolerance=10%, Voltage Rating=100V
C2 C9: "CAP, CERM, 1uF, 100V, +/-20%, X7R, 1206", Cap_Case=1206, Manufacturer=TDK, Supplier Part Number 1=445-4468-1-ND, TempCo=X7R, Tolerance_%=20, Value1=Unknown, Value2=100V, ValueDisplayed=1µF
C4 C5 C6: "CAP, CERM, 2.2 µF, 100 V, +/- 10%, X7R, 1210", Cap_Case=1210, Manufacturer=MuRata, Supplier Part Number 1=490-3385-1-ND, TempCo=X7R, Tolerance_%=10, Value1="0.007 ohm", Value2=100V, ValueDisplayed=2.2µF
C10: "CAP, CERM, 10 µF, 100 V, +/- 20%, X7R, 2220", Cap_Case=2220, Manufacturer=AVX, Supplier Part Number 1=478-9622-1-ND, TempCo=X7R, Tolerance_%=20, Value1=Unknown, Value2=100V, ValueDisplayed=10µF
C15: "CAP, CERM, 4.7 µF, 100 V, +/- 10%, X7S, 1210", Cap_Case=1210, Manufacturer=TDK, Supplier Part Number 1=445-8912-1-ND, TempCo=X7S, Tolerance_%=10, Value1=Unknown, Value2=100V, ValueDisplayed=4.7µF
C16: "CAP, CERM, 1 µF, 100 V, +/- 10%, X7S, 0805", Cap_Case=0805, Manufacturer=TDK, Supplier Part Number 1=445-5205-1-ND, TempCo=X7S, Tolerance_%=10, Value1="0.008255 ohm", Value2=100V, ValueDisplayed=1µF
C19: "CAP, CERM, 3.3 µF, 100 V, +/- 20%, X7S, 1206_190", Cap_Case=1206_190, Manufacturer=TDK, Supplier Part Number 1=445-9234-1-ND, TempCo=X7S, Tolerance_%=20, Value1="0.003048 ohm", Value2=100V, ValueDisplayed=3.3µF
C22 C35: "CAP, CERM, 100pF, 50V, +/-5%, C0G/NP0, 0402", Cap_Case=0402, Manufacturer="Yageo America", Supplier Part Number 1=311-1024-1-ND, TempCo=C0G/NP0, Tolerance_%=5, Value1=Unknown, Value2=50V, ValueDisplayed=100pF
C23 C25: "CAP, CERM, 10pF, 50V, +/-5%, C0G/NP0, 0402", Cap_Case=0402, Manufacturer=MuRata, Supplier Part Number 1=81-GRM1555C1H100JA1D, TempCo=C0G/NP0, Tolerance_%=5, Value1=Unknown, Value2=50V, ValueDisplayed=10pF
C24: library part CMP-08246-002729-1, "Multilayer Ceramic Capacitors 100nF ±10% 10V X5R SMD 0402", Capacitance=100nF, Case Code (Imperial)=0402, Case Code (Metric)=1005, Dielectric=X5R, Dielectric Material=Ceramic, Max Operating Temperature=85°C, Min Operating Temperature=-55°C, Package Quantity=1, Tolerance=10%, Voltage=10V
C26: "CAP, CERM, 0.1 µF, 16 V, +/- 5%, X7R, 0603", Cap_Case=0603, Manufacturer=AVX, Supplier Part Number 1=478-3726-1-ND, TempCo=X7R, Tolerance_%=5, Value1="0.039 ohm", Value2=16V, ValueDisplayed=0.1µF
C27: "CAP, CERM, 10uF, 25V, +/-10%, X5R, 0805", Cap_Case=0805, Manufacturer=TDK, Supplier Part Number 1=445-5984-1-ND, TempCo=X5R, Tolerance_%=10, Value1=Unknown, Value2=25V, ValueDisplayed=10µF
C28 C29: "CAP, CERM, 2.2uF, 16V, +/-10%, X7R, 0805", Cap_Case=0805, Manufacturer=Kemet, Supplier Part Number 1=399-3523-1-ND, TempCo=X7R, Tolerance_%=10, Value1="0.008 ohm", Value2=16V, ValueDisplayed=2.2µF
C30: "CAP, CERM, 1uF, 25V, +/-10%, X5R, 0402", Cap_Case=0402, Manufacturer=TDK, Supplier Part Number 1=445-9066-1-ND, TempCo=X5R, Tolerance_%=10, Value1=Unknown, Value2=25V, ValueDisplayed=1µF
C31: "CAP, CERM, 100pF, 25V, +/-10%, X7R, 0603", Alternate Manufacturer=-, Cap_Case=0603, Dielectric=X7R, Manufacturer=AVX, Tolerance_%=10, Value1=?, Value2=25V, ValueDisplayed=100pF
C32 C34: "CAP, CERM, 2.2uF, 10V, +/-10%, X7R, 0603", Cap_Case=0603, Dielectric=X7R, DigiKeyPartNumber=490-4520-1-ND, Manufacturer=MuRata, Tolerance_%=10, Value1="0.009 ohm", Value2=10V, ValueDisplayed=2.2µF
C36: "CAP, CERM, 15 µF, 100 V, +/- 20%, X7S, 2220", Cap_Case=2220_280, Manufacturer=TDK, Supplier Part Number 1=445-6044-1-ND, TempCo=X7S, Tolerance_%=20, Value1="0.002642 ohm", Value2=100V, ValueDisplayed=15µF
D1 D2: library part LTST-C170KGKT, "LED, Green, SMD", Color=Green, Manufacturer=Lite-On, Supplier Part Number 1=160-1414-1-ND, Value1=W, Value2=2V
D3 D4: "Diode, Schottky, 40V, 0.03A, SOD-523", Manufacturer="Diodes Inc.", Supplier Part Number 1=SDM03U40DICT-ND, Value1=0.03A, Value2=1V
H9 H10 H11 H12: "Bumpon, Hemisphere, 0.44 X 0.20, Clear", Manufacturer=3M, Supplier Part Number 1=SJ5303-7-ND
J1 J2: library part 282841-2, "Terminal Block, 2x1, 5.08mm, TH", Manufacturer="TE Connectivity", Supplier Part Number 1=A98342-ND
J3: "Terminal Block, 2x1, 2.54mm, TH", Manufacturer="TE Connectivity", Supplier Part Number 1=A98333-ND
J5: "Header, 100mil, 4x1, Tin, TH", Manufacturer="TE Connectivity", Supplier Part Number 1=5-146278-4-ND
J12: library part CMP-2000-05575-2, "PC TEST POINT MINIATURE YELLOW", Manufacturer=Keystone
L1: library part XAL8080-472ME, "Inductor, Shielded, Composite, 4.7 µH, 10.5 A, 0.00889 ohm, SMD", Manufacturer=Coilcraft, Supplier Part Number 1=994-XAL1010-472MED, Value1="0.00889 ohm", Value2=10.5A, ValueDisplayed=4.7µH
Logo1: library part TI_Logo, "Texas Instrument Corporate Signature"
LOGO2 LOGO2b: library part IEC_HighVoltage, "IEC 61010-1 High Voltage Warning"
LOGO3 LOGO3b: library part IEC_HotSurface, "IEC 61010-1 Hot Surface Warning"
Logo4: library part FCC_disclaimer, "FCC_disclaimer"
Logo5: library part Pb-Free
NT1 NT3: "Single point connection between nets."
R1: "RES, 1.0k ohm, 5%, 0.1W, 0603", Manufacturer=Vishay-Dale, Power_W=0.1, Supplier Part Number 1=71-CRCW0603J-1.0K-E3, TempCo="200 ppm/C", Tolerance_%=5, Value1=5%, Value2=0.1W, Value_Code=1k00
R2 R14: "RES, 47 ohm, 5%, 0.063W, 0402", Manufacturer=Vishay-Dale, Power_W=0.063, Supplier Part Number 1=541-47JCT-ND, TempCo="200 ppm/C", Tolerance_%=5, Value1=5%, Value2=0.063W, Value_Code=47R0
R3: "RES, 10.0k ohm, 1%, 0.063W, 0402", Manufacturer=Vishay-Dale, Power_W=0.063, Supplier Part Number 1=541-10.0KLCT-ND, TempCo="100 ppm/C", Tolerance_%=1, Value1=1%, Value2=0.063W, Value_Code=10k0
R4: "RES, 20k ohm, 5%, 0.25W, 1206", Manufacturer=Vishay-Dale, Power_W=0.25, Supplier Part Number 1=541-20KECT-ND, TempCo="200 ppm/C", Tolerance_%=5, Value1=5%, Value2=0.25W, Value_Code=20k0
R5 R8: library part CMP-1011-00259-3, "RES Thick Film, 6.04Ω, 1%, 0.063W, 100ppm/°C, 0402", Case Code (Imperial)=0402, Case Code (Metric)=1005, Max Operating Temperature=155°C, Max Power Dissipation=63mW, Min Operating Temperature=-55°C, Package Quantity=10, Resistance=6.04R, Temperature Coefficient=100ppm/°C, Tolerance=1%, Voltage Rating=50V
R6 R7 R10: "RES, 0 ohm, 5%, 0.1W, 0603", Manufacturer=Vishay-Dale, Power_W=0.1, Supplier Part Number 1=541-0.0GCT-ND, TempCo="200 ppm/C", Tolerance_%=5, Value1=5%, Value2=0.1W, Value_Code=0000
R11 R12 R13: "RES, 0 ohm, 5%, 0.063W, 0402", Manufacturer=Vishay-Dale, Power_W=0.063, Supplier Part Number 1=541-0.0JCT-ND, TempCo="200 ppm/C", Tolerance_%=5, Value1=5%, Value2=0.063W, Value_Code=0000
TP1: "Test Point, Miniature, Red, TH", Manufacturer=Keystone, Supplier Part Number 1=5000K-ND
TP2: library part 5000, "Test Point, Miniature, Red, TH", Manufacturer=Keystone, Supplier Part Number 1=5000K-ND
TP3: library part 5001, "Test Point, Miniature, Black, TH", Manufacturer=Keystone, Supplier Part Number 1=5001K-ND
TP4 TP7: "Test Point, Miniature, Black, TH", Manufacturer=Keystone, Supplier Part Number 1=5001K-ND
TP6: "Test Point, Miniature, Yellow, TH", Color=Yellow, Manufacturer=Keystone, Supplier Part Number 1=36-5004-ND
U1: library part CMP-0097820-2, Manufacturer="Texas Instruments", Operating Temperature Range=to
U2: "1A Low Dropout CMOS Linear Regulators Stable with Ceramic Output Capacitors, 6-pin LLP, Pb-Free", Manufacturer="Texas Instruments", PackageTopMarking=ZXYTT*L116B, PowerWise=Y, Supplier Part Number 1=LP38690SD-5.0TR-ND
U3: "Triple Schmitt-Trigger Inverter, DCU0008A", Alternate Manufacturer="Texas Instruments", Alternate PartNumber=SN74LVC3G14DCUT
U4: "Dual Schmitt-Trigger Inverter, YZP0006ADBD (DSBGA-6)", Alternate Manufacturer="Texas Instruments"
ZZ2 ZZ3 ZZ4: library part AssemblyNote, Alternate Manufacturer=-

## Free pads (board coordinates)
  round 145.67 hole 137.8: 2(477.99,1697.61) 2(1434.53,1165.31)

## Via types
v1: diameter 24, hole 12, Top Layer to Bottom Layer, tented both sides, 201 vias
v2: diameter 19.68, hole 7.87, Top Layer to Bottom Layer, tented both sides, 15 vias
v3: diameter 18, hole 8, Top Layer to Bottom Layer, tented both sides, 13 vias
v4: diameter 18, hole 8, Top Layer to Bottom Layer, 9 vias
v5: diameter 19.68, hole 7.87, Top Layer to Bottom Layer, 4 vias
v6: diameter 32, hole 20, Top Layer to Bottom Layer, 2 vias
